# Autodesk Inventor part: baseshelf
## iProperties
Created: 2005-05
Part Number: baseshelf
Material: cherry
Document SubType Name: Modeling
Designer: a.campbell
Manufacturer: Standard
Standards Organization: Custom
length: 338
thickness: 19
width: 423
Author: a.campbell
Comments: machine to detail
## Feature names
1. Extrusion1
2. Extrusion2
